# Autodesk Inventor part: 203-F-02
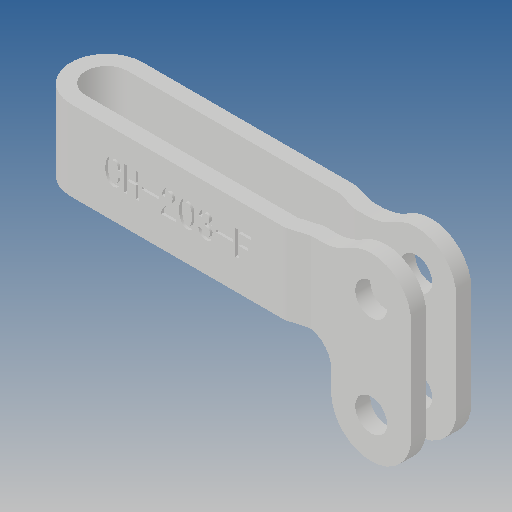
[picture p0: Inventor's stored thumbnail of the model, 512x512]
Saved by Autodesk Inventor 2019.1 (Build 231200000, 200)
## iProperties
Created: 2011-05
Part Number: 203-F-02
Material: Ogólny
Document SubType Name: Modeling
Designer: CADENGINEERING4
Density: 1 g/cm^3
Appearance: Domyślna
Author: CADENGINEERING4
Revision Number: ÈÎºÎ
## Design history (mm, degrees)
feature "ÇÐ³ý-À­Éì4"
node "Bryła1"
